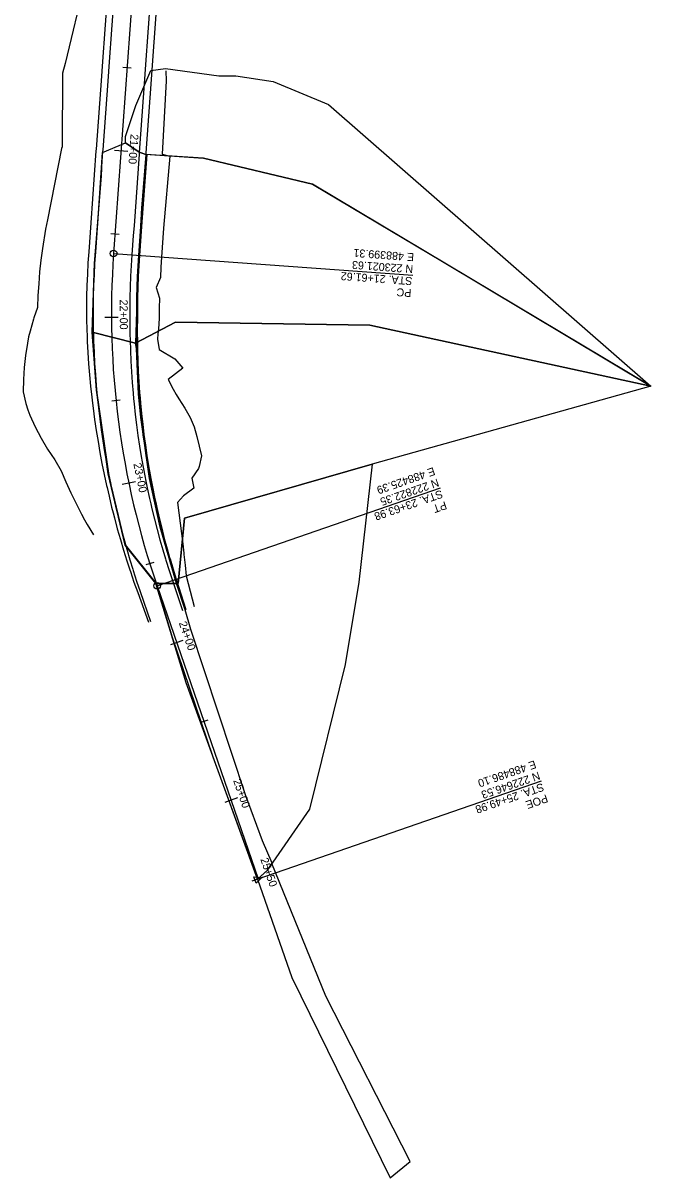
# Model space of a CAD drawing. Extents: x 487756 to 488722, y 222467 to 224000.
# Drawn here: x 488345 to 488722, y 222467 to 223160 of the extents above; entities that cross this region are included whole.
import ezdxf

# ---------------------------------------------------------------- set-up
doc = ezdxf.new("R2010")
doc.units = 0
for name, color, linetype in [('HD-SURF-MISC', 7, 'Continuous'), ('HM-SMOD-BRK LINE', 7, 'Continuous'), ('HR-FEAT-BCPC', 7, 'Continuous'), ('HR-FEAT-CUT', 7, 'Continuous'), ('HR-FEAT-EOR', 7, 'Continuous'), ('HR-FEAT-FILL', 7, 'Continuous'), ('HR-GMSC-HOR_VER ALN', 7, 'Continuous'), ('HR-GMSC-PCPT SYMB', 7, 'Continuous'), ('HR-GPLN-CL STA', 7, 'Continuous'), ('HR-GPLN-CL TICKS', 7, 'Continuous'), ('HR-GPLN-PCPT LDR', 7, 'Continuous'), ('HR-GPLN-PCPT TXT', 7, 'Continuous'), ('HR-GPLN-PI SYM', 7, 'Continuous'), ('SV_MISC_MISC_TOPO', 7, 'Continuous')]:
    doc.layers.add(name, color=color, linetype=linetype)

msp = doc.modelspace()

# ---------------------------------------------------------------- linework, layer by layer
at = {"layer": 'HD-SURF-MISC'}
for points in [[(488495.18, 223124.79), (488528.35, 223111.05), (488721.84, 222942.12), (488518.67, 223063.28), (488453.3, 223078.89), (488418.63, 223081.13), (488414.58, 223082.55), (488406.47, 223088.04), (488406.53, 223091.82), (488412.6, 223110.54), (488421.62, 223131.39), (488430.36, 223132.7), (488462.54, 223128.19), (488472.69, 223128.32)], [(488392.68, 223082.18), (488406.47, 223088.04), (488414.45, 223082.65), (488418.63, 223081.13), (488416, 223048.83), (488413.59, 223006.23), (488412.39, 222967.89), (488386.36, 222974.51), (488387.9, 223015.76), (488392, 223068.17)], [(488389.85, 223039.72), (488392.68, 223082.18), (488406.47, 223088.04), (488414.58, 223082.55), (488418.32, 223081.18), (488453.3, 223078.89), (488518.67, 223063.28), (488596.73, 223016.83), (488721.84, 222942.12), (488553.05, 222978.59), (488436.52, 222980.53), (488412.39, 222967.89), (488386.36, 222974.51), (488387.89, 223015.94)], [(488721.84, 222942.12), (488554.51, 222895.31), (488441.81, 222862.95), (488437.97, 222823.71), (488424.68, 222823.72), (488406.22, 222846.83), (488396.1, 222889.48), (488389.01, 222939.76), (488386.36, 222974.51), (488412.39, 222967.89), (488436.52, 222980.53), (488553.05, 222978.59)], [(488386.36, 222974.51), (488388.98, 222939.29), (488396.65, 222887.05), (488406.32, 222846.85), (488424.8, 222823.72), (488437.11, 222823.72), (488427.33, 222857.45), (488420.94, 222886.79), (488415.61, 222923.35), (488414.34, 222937.39), (488413.07, 222964.62), (488412.39, 222967.89)], [(488554.51, 222895.31), (488546.49, 222824.55), (488538.34, 222775.23), (488516.84, 222688.42), (488491.29, 222651.44), (488485.64, 222646.49), (488464.44, 222704.69), (488442.78, 222764.18), (488424.68, 222823.72), (488437.97, 222823.71), (488441.81, 222862.95)], [(488424.75, 222823.66), (488434.31, 222792.18), (488458.9, 222719.77), (488485.64, 222646.49), (488491.68, 222651.85), (488494.49, 222655.98), (488488.63, 222669.45), (488478.46, 222696.98), (488445.73, 222796.13), (488442.19, 222808), (488437.11, 222823.71)], [(488485.64, 222646.49), (488506.31, 222587.44), (488565.24, 222467.22), (488577.33, 222477.15), (488526.77, 222576.2), (488494.22, 222655.73), (488491.29, 222651.44)]]:
    msp.add_lwpolyline(points, close=True, dxfattribs=at)
at = {"layer": 'HM-SMOD-BRK LINE'}
for points in [[(488400, 223183.62), (488396.39, 223133.76), (488395.96, 223127.82), (488392.78, 223083.89), (488392.71, 223082.89), (488389.59, 223039.78), (488389.18, 223034.02), (488388.34, 223022.42), (488387.9, 223015.76), (488387.55, 223009.1), (488387.28, 223002.44), (488387.11, 222995.77), (488387.02, 222989.1), (488387.01, 222983.23), (488387.02, 222982.43), (488387.11, 222975.76), (488387.19, 222972.58), (488387.29, 222969.09), (488387.56, 222962.42), (488387.92, 222955.76), (488388.36, 222949.1), (488388.89, 222942.46), (488389.51, 222935.81), (488389.88, 222932.24), (488390.21, 222929.18), (488391, 222922.56), (488391.88, 222915.95), (488392.84, 222909.35), (488393.89, 222902.76), (488395.02, 222896.19), (488396.24, 222889.63), (488397.55, 222883.09), (488397.82, 222881.79), (488398.94, 222876.57), (488400.41, 222870.06), (488401.22, 222866.66), (488401.97, 222863.58), (488403.62, 222857.12), (488405.35, 222850.68), (488407.16, 222844.26), (488409.06, 222837.87), (488410.75, 222832.4), (488411.04, 222831.5), (488413.1, 222825.16), (488415.25, 222818.85), (488421.48, 222800.88)], [(488421.94, 223182.04), (488418.34, 223132.17), (488417.91, 223126.23), (488414.73, 223082.3), (488414.66, 223081.3), (488411.54, 223038.19), (488411.12, 223032.43), (488410.28, 223020.83), (488409.86, 223014.46), (488409.53, 223008.09), (488409.27, 223001.71), (488409.1, 222995.33), (488409.02, 222988.94), (488409.01, 222983.33), (488409.01, 222982.56), (488409.04, 222976.18), (488409.08, 222973.14), (488409.15, 222969.79), (488409.35, 222963.41), (488409.63, 222957.03), (488410, 222950.65), (488410.44, 222944.28), (488410.97, 222937.91), (488411.29, 222934.49), (488411.59, 222931.55), (488412.28, 222925.2), (488413.06, 222918.86), (488413.93, 222912.53), (488414.87, 222906.2), (488415.9, 222899.9), (488417.01, 222893.6), (488418.2, 222887.32), (488418.45, 222886.07), (488419.48, 222881.05), (488420.83, 222874.8), (488421.58, 222871.53), (488422.27, 222868.57), (488423.79, 222862.36), (488425.39, 222856.16), (488427.07, 222849.99), (488428.83, 222843.84), (488430.41, 222838.58), (488430.68, 222837.71), (488432.6, 222831.61), (488434.6, 222825.53), (488440.67, 222807.51)]]:
    msp.add_lwpolyline(points, dxfattribs=at)
at = {"layer": 'HR-FEAT-BCPC'}
msp.add_lwpolyline([(488419.23, 223080.97), (488416.11, 223037.86), (488415.69, 223032.1), (488414.85, 223020.5), (488414.44, 223014.19), (488414.1, 223007.88), (488413.85, 223001.56), (488413.69, 222995.24), (488413.6, 222988.91), (488413.59, 222983.35), (488413.58, 222982.59), (488413.53, 222976.26), (488413.53, 222973.25), (488413.55, 222969.93), (488413.66, 222963.6), (488413.86, 222957.28), (488414.13, 222950.95), (488414.49, 222944.62), (488414.93, 222938.3), (488415.2, 222934.9), (488415.45, 222931.98), (488416.06, 222925.67), (488416.75, 222919.37), (488417.52, 222913.07), (488418.37, 222906.78), (488419.31, 222900.5), (488420.32, 222894.23), (488421.42, 222887.98), (488421.65, 222886.74), (488422.61, 222881.74), (488423.87, 222875.51), (488424.57, 222872.25), (488425.22, 222869.29), (488426.64, 222863.1), (488428.15, 222856.92), (488429.74, 222850.76), (488431.41, 222844.62), (488432.91, 222839.37), (488433.16, 222838.5), (488434.99, 222832.4), (488436.9, 222826.32), (488442.74, 222808.22)], dxfattribs=at)
at = {"layer": 'HR-FEAT-CUT'}
msp.add_lwpolyline([(488428.45, 223081.31), (488433.14, 223079.96), (488429.19, 223036.91), (488428.75, 223031.15), (488428.08, 223019.55), (488427.73, 223013.41), (488427.35, 223007.27), (488424.88, 223001.19), (488426.76, 222994.97), (488426.68, 222988.82), (488426.59, 222983.41), (488426.58, 222982.67), (488426.31, 222976.51), (488425.8, 222973.56), (488425.67, 222970.32), (488426.65, 222964.19), (488436.05, 222958.57), (488440.89, 222952.86), (488432.08, 222946.11), (488434.99, 222940.26), (488436.87, 222937.17), (488438.51, 222934.54), (488441.98, 222928.89), (488445.34, 222923.3), (488447.66, 222917.61), (488449.25, 222911.85), (488450.69, 222906.08), (488452.13, 222900.31), (488450.67, 222893.97), (488450.28, 222892.68), (488446.31, 222886.91), (488447.51, 222880.99), (488441.35, 222876.26), (488437.63, 222872.35), (488438.53, 222866.19), (488439.3, 222859.97), (488440.04, 222853.72), (488440.77, 222847.45), (488441.38, 222842.03), (488441.48, 222841.13), (488442.18, 222834.78), (488442.87, 222828.38), (488447.57, 222809.89)], dxfattribs=at)
at = {"layer": 'HR-FEAT-EOR'}
for points in [[(488396.01, 223183.91), (488392.4, 223134.04), (488391.97, 223128.11), (488388.8, 223084.17), (488388.72, 223083.18), (488385.6, 223040.07), (488385.19, 223034.3), (488384.35, 223022.71), (488383.91, 223016), (488383.55, 223009.29), (488383.29, 223002.57), (488383.11, 222995.85), (488383.02, 222989.13), (488383.01, 222983.22), (488383.03, 222982.4), (488383.22, 222975.68), (488383.34, 222972.48), (488383.5, 222968.97), (488383.87, 222962.25), (488384.32, 222955.55), (488384.86, 222948.85), (488385.49, 222942.17), (488386.21, 222935.49), (488386.63, 222931.9), (488387.01, 222928.83), (488387.9, 222922.17), (488388.88, 222915.53), (488389.94, 222908.91), (488391.09, 222902.3), (488392.33, 222895.71), (488393.65, 222889.13), (488395.06, 222882.58), (488395.35, 222881.28), (488396.55, 222876.05), (488398.12, 222869.53), (488398.98, 222866.13), (488399.79, 222863.04), (488401.53, 222856.57), (488403.36, 222850.13), (488405.27, 222843.72), (488407.27, 222837.33), (488409.05, 222831.87), (488409.35, 222830.96), (488411.51, 222824.63), (488413.75, 222818.33), (488420.25, 222800.45)], [(488425.93, 223181.75), (488422.32, 223131.88), (488421.9, 223125.94), (488418.72, 223082.01), (488418.64, 223081.01), (488415.53, 223037.9), (488415.11, 223032.14), (488414.27, 223020.55), (488413.85, 223014.23), (488413.52, 223007.9), (488413.27, 223001.58), (488413.1, 222995.25), (488413.02, 222988.92), (488413.01, 222983.35), (488413, 222982.59), (488412.94, 222976.25), (488412.95, 222973.24), (488412.97, 222969.91), (488413.08, 222963.58), (488413.27, 222957.24), (488413.55, 222950.91), (488413.91, 222944.57), (488414.35, 222938.24), (488414.62, 222934.84), (488414.87, 222931.92), (488415.48, 222925.6), (488416.17, 222919.29), (488416.94, 222912.98), (488417.8, 222906.69), (488418.73, 222900.4), (488419.75, 222894.12), (488420.85, 222887.86), (488421.08, 222886.62), (488422.04, 222881.61), (488423.3, 222875.38), (488424, 222872.11), (488424.65, 222869.16), (488426.08, 222862.95), (488427.59, 222856.77), (488429.18, 222850.6), (488430.85, 222844.45), (488432.35, 222839.19), (488432.6, 222838.32), (488434.44, 222832.22), (488436.35, 222826.13), (488442.18, 222808.03)]]:
    msp.add_lwpolyline(points, dxfattribs=at)
at = {"layer": 'HR-FEAT-FILL'}
for points in [[(488381.95, 223184.93), (488370.13, 223135.66), (488368.66, 223129.79), (488368.35, 223085.65), (488368.1, 223084.67), (488359.57, 223041.95), (488358.37, 223036.25), (488356.54, 223024.72), (488355.57, 223017.68), (488354.88, 223010.61), (488354.33, 223003.53), (488353.83, 222996.43), (488353.6, 222989.33), (488351.51, 222983.07), (488351.24, 222982.21), (488349.17, 222975.03), (488348.29, 222971.59), (488347.57, 222967.81), (488346.43, 222960.56), (488345.61, 222953.29), (488345.12, 222946.01), (488344.95, 222938.74), (488346.6, 222931.62), (488347.79, 222927.82), (488349.04, 222924.61), (488352.21, 222917.74), (488355.78, 222910.98), (488359.69, 222904.34), (488363.94, 222897.84), (488367.78, 222891.35), (488370.56, 222884.72), (488373.63, 222878.19), (488374.27, 222876.91), (488376.74, 222871.72), (488380.02, 222865.33), (488381.79, 222862.01), (488383.49, 222859.03), (488387.26, 222852.87)], [(488430.65, 223131.28), (488430.93, 223125.29), (488428.45, 223081.31)]]:
    msp.add_lwpolyline(points, dxfattribs=at)
at = {"layer": 'HR-GMSC-HOR_VER ALN'}
for p, q in [((488411.38, 223188.4), (488399.31, 223021.63)), ((488425.39, 222822.35), (488486.1, 222646.53))]:
    msp.add_line(p, q, dxfattribs=at)
msp.add_arc((488898.01, 222985.55), 500, 175.86194, 199.05038, dxfattribs=at)
at = {"layer": 'HR-GMSC-PCPT SYMB'}
for centre in [(488399.31, 223021.63), (488425.39, 222822.35)]:
    msp.add_circle(centre, 2, dxfattribs=at)
at = {"layer": 'HR-GPLN-CL TICKS'}
for points in [[(488409.86, 223132.78), (488404.87, 223133.14)], [(488407.75, 223082.8), (488399.77, 223083.38)], [(488402.64, 223033.04), (488397.65, 223033.4)], [(488402.01, 222983.3), (488394.01, 222983.27)], [(488403.22, 222933.64), (488398.25, 222933.12)], [(488412.34, 222884.81), (488404.51, 222883.18)], [(488423.4, 222836.38), (488418.63, 222834.88)], [(488440.93, 222789.61), (488433.37, 222787)], [(488455.83, 222741.86), (488451.1, 222740.23)], [(488473.57, 222695.09), (488466.01, 222692.47)], [(488489.88, 222647.84), (488482.32, 222645.23)], [(488488.46, 222647.35), (488483.74, 222645.72)]]:
    msp.add_lwpolyline(points, dxfattribs=at)
at = {"layer": 'HR-GPLN-PCPT LDR'}
for points in [[(488399.31, 223021.63), (488578.84, 223008.64)], [(488425.39, 222822.35), (488595.53, 222881.1)], [(488486.1, 222646.53), (488656.24, 222705.29)]]:
    msp.add_lwpolyline(points, dxfattribs=at)
at = {"layer": 'HR-GPLN-PI SYM'}
msp.add_lwpolyline([(488487.99, 222647.19), (488484.86, 222643.99), (488483.56, 222647.77)], close=True, dxfattribs=at)
at = {"layer": 'SV_MISC_MISC_TOPO'}
for p, q in [((488370.13, 223135.66), (488370.13, 223135.66)), ((488430.65, 223131.28), (488430.65, 223131.28)), ((488368.66, 223129.79), (488368.66, 223129.79)), ((488430.93, 223125.29), (488430.93, 223125.29)), ((488368.1, 223084.67), (488368.1, 223084.67)), ((488368.35, 223085.65), (488368.35, 223085.65)), ((488428.45, 223081.31), (488428.45, 223081.31)), ((488433.14, 223079.96), (488433.14, 223079.96)), ((488359.57, 223041.95), (488359.57, 223041.95)), ((488358.37, 223036.25), (488358.37, 223036.25)), ((488429.19, 223036.91), (488429.19, 223036.91)), ((488428.75, 223031.15), (488428.75, 223031.15)), ((488356.54, 223024.72), (488356.54, 223024.72)), ((488355.57, 223017.68), (488355.57, 223017.68)), ((488427.73, 223013.41), (488427.73, 223013.41)), ((488428.08, 223019.55), (488428.08, 223019.55)), ((488354.88, 223010.61), (488354.88, 223010.61)), ((488427.35, 223007.27), (488427.35, 223007.27)), ((488354.33, 223003.53), (488354.33, 223003.53)), ((488424.88, 223001.19), (488424.88, 223001.19)), ((488353.83, 222996.43), (488353.83, 222996.43)), ((488426.76, 222994.97), (488426.76, 222994.97)), ((488353.6, 222989.33), (488353.6, 222989.33)), ((488426.68, 222988.82), (488426.68, 222988.82)), ((488351.24, 222982.21), (488351.24, 222982.21)), ((488351.51, 222983.07), (488351.51, 222983.07)), ((488426.58, 222982.67), (488426.58, 222982.67)), ((488426.59, 222983.41), (488426.59, 222983.41)), ((488348.29, 222971.59), (488348.29, 222971.59)), ((488349.17, 222975.03), (488349.17, 222975.03)), ((488425.8, 222973.56), (488425.8, 222973.56)), ((488426.31, 222976.51), (488426.31, 222976.51)), ((488347.57, 222967.81), (488347.57, 222967.81)), ((488425.67, 222970.32), (488425.67, 222970.32)), ((488426.65, 222964.19), (488426.65, 222964.19)), ((488346.43, 222960.56), (488346.43, 222960.56)), ((488436.05, 222958.57), (488436.05, 222958.57)), ((488345.61, 222953.29), (488345.61, 222953.29)), ((488440.89, 222952.86), (488440.89, 222952.86)), ((488345.12, 222946.01), (488345.12, 222946.01)), ((488432.08, 222946.11), (488432.08, 222946.11)), ((488344.95, 222938.74), (488344.95, 222938.74)), ((488434.99, 222940.26), (488434.99, 222940.26)), ((488436.87, 222937.17), (488436.87, 222937.17)), ((488346.6, 222931.62), (488346.6, 222931.62)), ((488438.51, 222934.54), (488438.51, 222934.54)), ((488347.79, 222927.82), (488347.79, 222927.82)), ((488349.04, 222924.61), (488349.04, 222924.61)), ((488441.98, 222928.89), (488441.98, 222928.89)), ((488445.34, 222923.3), (488445.34, 222923.3)), ((488352.21, 222917.74), (488352.21, 222917.74)), ((488447.66, 222917.61), (488447.66, 222917.61)), ((488355.78, 222910.98), (488355.78, 222910.98)), ((488449.25, 222911.85), (488449.25, 222911.85)), ((488359.69, 222904.34), (488359.69, 222904.34)), ((488450.69, 222906.08), (488450.69, 222906.08)), ((488363.94, 222897.84), (488363.94, 222897.84)), ((488452.13, 222900.31), (488452.13, 222900.31)), ((488367.78, 222891.35), (488367.78, 222891.35)), ((488450.28, 222892.68), (488450.28, 222892.68)), ((488450.67, 222893.97), (488450.67, 222893.97)), ((488370.56, 222884.72), (488370.56, 222884.72)), ((488446.31, 222886.91), (488446.31, 222886.91)), ((488373.63, 222878.19), (488373.63, 222878.19)), ((488374.27, 222876.91), (488374.27, 222876.91)), ((488441.35, 222876.26), (488441.35, 222876.26)), ((488447.51, 222880.99), (488447.51, 222880.99)), ((488376.74, 222871.72), (488376.74, 222871.72)), ((488437.63, 222872.35), (488437.63, 222872.35)), ((488380.02, 222865.33), (488380.02, 222865.33)), ((488381.79, 222862.01), (488381.79, 222862.01)), ((488438.53, 222866.19), (488438.53, 222866.19)), ((488383.49, 222859.03), (488383.49, 222859.03)), ((488439.3, 222859.97), (488439.3, 222859.97)), ((488440.04, 222853.72), (488440.04, 222853.72)), ((488387.26, 222852.87), (488387.26, 222852.87)), ((488403.36, 222850.13), (488403.36, 222850.13)), ((488440.77, 222847.45), (488440.77, 222847.45)), ((488405.27, 222843.72), (488405.27, 222843.72)), ((488441.38, 222842.03), (488441.38, 222842.03)), ((488441.48, 222841.13), (488441.48, 222841.13)), ((488407.27, 222837.33), (488407.27, 222837.33)), ((488442.18, 222834.78), (488442.18, 222834.78)), ((488409.05, 222831.87), (488409.05, 222831.87)), ((488409.35, 222830.96), (488409.35, 222830.96)), ((488442.87, 222828.38), (488442.87, 222828.38)), ((488411.51, 222824.63), (488411.51, 222824.63)), ((488413.75, 222818.33), (488413.75, 222818.33)), ((488440.67, 222807.51), (488440.67, 222807.51)), ((488442.18, 222808.03), (488442.18, 222808.03)), ((488442.18, 222808.03), (488442.18, 222808.03)), ((488442.51, 222808.14), (488442.51, 222808.14)), ((488442.74, 222808.22), (488442.74, 222808.22)), ((488445.96, 222809.33), (488445.96, 222809.33)), ((488447.57, 222809.89), (488447.57, 222809.89)), ((488420.25, 222800.45), (488420.25, 222800.45)), ((488421.48, 222800.88), (488421.48, 222800.88)), ((488431.6, 222804.37), (488431.6, 222804.37))]:
    msp.add_line(p, q, dxfattribs=at)

# ---------------------------------------------------------------- texts
at = {"layer": 'HR-GPLN-CL STA'}
for s, rotation, p in [('21+00', 265.86194, (488409.52, 223093.44)), ('22+00', 270.25944, (488402.96, 222994.05)), ('23+00', 281.71859, (488411.14, 222895.53)), ('24+00', 289.05038, (488438.37, 222800.09)), ('25+00', 289.05038, (488471.01, 222705.57)), ('25+50', 289.05038, (488487.32, 222658.32))]:
    msp.add_text(s, height=4.8, rotation=rotation, dxfattribs=at).set_placement(p)
at = {"layer": 'HR-GPLN-PCPT TXT'}
for s, rotation, p in [('E 488399.31', 175.86194, (488579.79, 223021.8)), ('N 223021.63', 175.86194, (488579.27, 223014.62)), ('STA. 21+61.62', 175.86194, (488578.75, 223007.44)), ('PC ', 175.86194, (488578.23, 223000.26)), ('E 488425.39', 199.05038, (488591.22, 222893.58)), ('N 222822.35', 199.05038, (488593.57, 222886.77)), ('STA. 23+63.98', 199.05038, (488595.92, 222879.97)), ('PT ', 199.05038, (488598.27, 222873.16)), ('E 488486.10', 199.05038, (488651.93, 222717.76)), ('N 222646.53', 199.05038, (488654.28, 222710.96)), ('STA. 25+49.98', 199.05038, (488656.63, 222704.15)), ('POE ', 199.05038, (488658.98, 222697.35))]:
    msp.add_text(s, height=4.8, rotation=rotation, dxfattribs=at).set_placement(p)

doc.saveas('drawing.dxf')
